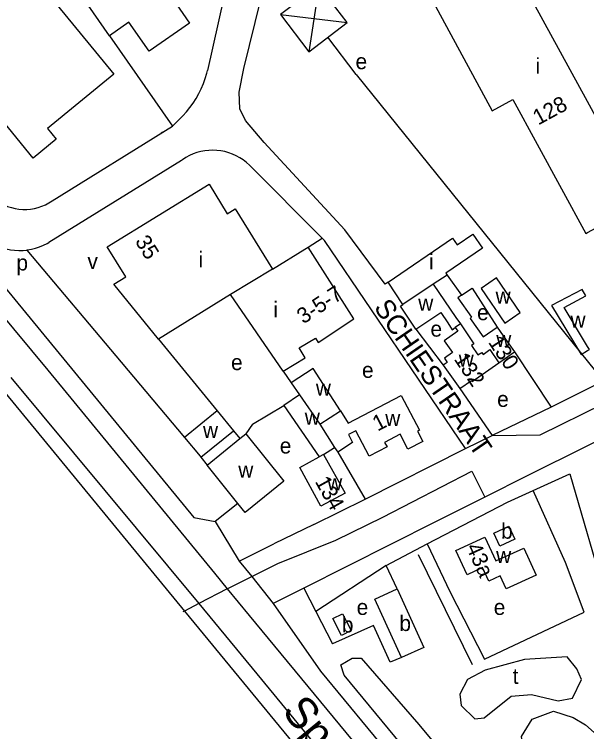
# Model space of a CAD drawing. Extents: x 156721 to 158827, y 386657 to 388950.
# Drawn here: x 157353.3 to 157499.8, y 387526.7 to 387710.2 of the extents above; entities that cross this region are included whole.
import ezdxf

# ---------------------------------------------------------------- set-up
doc = ezdxf.new("R2010")
doc.units = 0
for name, color, linetype in [('BLT_Basislijn', 7, 'Continuous'), ('BLT_Bebouwing', 7, 'Continuous'), ('BLT_Centroide', 7, 'Continuous'), ('BLT_Hoogspanningsmast_en_leidingen', 7, 'Continuous'), ('BLT_Huisnummer', 7, 'Continuous'), ('BLT_Huisnummer_reeks', 7, 'Continuous'), ('BLT_Onderverdeling_panden', 7, 'Continuous'), ('BLT_Spoorlijn', 7, 'Continuous'), ('BLT_Straatnaam', 7, 'Continuous'), ('BLT_Vlakafsluiter', 7, 'Continuous'), ('BLT_Waternaam_spoorwegen', 7, 'Continuous')]:
    doc.layers.add(name, color=color, linetype=linetype)

msp = doc.modelspace()

# ---------------------------------------------------------------- linework, layer by layer
at = {"layer": 'BLT_Basislijn'}
for p, q in [((157410.11, 387729.09), (157402.7, 387695.87)), ((157377.66, 387704.77), (157393.78, 387681.64)), ((157362.98, 387662.49), (157393.78, 387681.64)), ((157396.05, 387672.83), (157362.12, 387651.86)), ((157432.11, 387652.93), (157413.45, 387671.63)), ((157428.48, 387650.64), (157432.11, 387652.93)), ((157356.47, 387649.92), (157380.61, 387621.23)), ((157487.91, 387602.63), (157551.59, 387634.32)), ((157456.09, 387629.7), (157463.07, 387620.46)), ((157531.34, 387630.01), (157490.71, 387609.75)), ((157390.18, 387627.11), (157405.22, 387608.74)), ((157481.29, 387623.9), (157490.71, 387609.75)), ((157380.61, 387621.23), (157396.84, 387601.94)), ((157422.11, 387618.92), (157424.18, 387615.97)), ((157467.28, 387614.46), (157475.55, 387602.45)), ((157414.26, 387605.38), (157422.26, 387610.15)), ((157490.71, 387609.75), (157475.55, 387602.45)), ((157414.26, 387605.38), (157412.54, 387602.88)), ((157409.38, 387603.66), (157411.02, 387601.66)), ((157475.55, 387602.45), (157487.91, 387602.63)), ((157443.08, 387586.2), (157468.77, 387599.15)), ((157436.05, 387598.19), (157443.08, 387586.2)), ((157401.05, 387596.92), (157402.62, 387594.92)), ((157470.39, 387593.34), (157473.69, 387586.73)), ((157484.56, 387592.19), (157473.69, 387586.73)), ((157486.04, 387588.39), (157495.47, 387592.66)), ((157479.52, 387585.43), (157486.04, 387588.39)), ((157429.93, 387579.68), (157443.08, 387586.2)), ((157473.69, 387586.73), (157460.93, 387580.31)), ((157410.52, 387585.07), (157404.73, 387580.46)), ((157458.95, 387574.71), (157479.52, 387585.43)), ((157404.73, 387580.46), (157410.84, 387570.35)), ((157429.93, 387579.68), (157419.68, 387574.71)), ((157460.93, 387580.31), (157427.36, 387563.43)), ((157410.84, 387570.35), (157419.4, 387574.58)), ((157419.4, 387574.58), (157419.68, 387574.71)), ((157448.47, 387569.22), (157458.95, 387574.71)), ((157456.65, 387572.01), (157470.49, 387543.88)), ((157410.84, 387570.35), (157414.06, 387566.36)), ((157414.06, 387566.36), (157420.7, 387569.69)), ((157448.47, 387569.22), (157430.47, 387557.43)), ((157451.27, 387563.26), (157448.47, 387569.22)), ((157414.06, 387566.36), (157419.58, 387559.52)), ((157427.36, 387563.43), (157419.58, 387559.52)), ((157427.36, 387563.43), (157430.47, 387557.43)), ((157430.47, 387557.43), (157434.73, 387549.18))]:
    msp.add_line(p, q, dxfattribs=at)
for points in [[(157166.18, 387865.29), (157399.27, 387581.46), (157404.73, 387580.46)], [(157448.94, 387641.7), (157448.24, 387641.22), (157437.86, 387655.06), (157417.27, 387677.44), (157412.48, 387683.06), (157411.05, 387686.03), (157410.8, 387690.3), (157412, 387696.4), (157429.48, 387767.11), (157430.68, 387770.62), (157433.63, 387777.77)], [(157393.78, 387681.64), (157396.43, 387684.24), (157397.37, 387685.29), (157398.26, 387686.38), (157399.08, 387687.53), (157399.83, 387688.72), (157400.52, 387689.95), (157401.14, 387691.22), (157401.68, 387692.52), (157402.15, 387693.85), (157402.54, 387695.2), (157402.7, 387695.87)], [(157390.9, 387679.9), (157391.29, 387680.15)], [(157413.45, 387671.63), (157412.68, 387672.33), (157411.86, 387672.97), (157411, 387673.54), (157410.09, 387674.04), (157409.15, 387674.47), (157408.18, 387674.83), (157407.18, 387675.11), (157406.17, 387675.31), (157405.14, 387675.43), (157404.1, 387675.48), (157403.07, 387675.44), (157402.04, 387675.32), (157401.02, 387675.13), (157400.02, 387674.86), (157399.05, 387674.51), (157398.1, 387674.09), (157397.19, 387673.59), (157396.33, 387673.03), (157396.05, 387672.83)], [(157346.71, 387664.42), (157347.4, 387663.71), (157348.15, 387663.05), (157348.95, 387662.46), (157349.79, 387661.93), (157350.68, 387661.47), (157351.6, 387661.09), (157352.54, 387660.78), (157353.51, 387660.54), (157354.49, 387660.39), (157355.49, 387660.31), (157356.48, 387660.32), (157357.48, 387660.4), (157358.46, 387660.56), (157359.43, 387660.8), (157360.37, 387661.12), (157361.28, 387661.52), (157362.17, 387661.98), (157362.98, 387662.49)], [(157342.54, 387656.22), (157343.18, 387655.34), (157343.89, 387654.52), (157344.65, 387653.75), (157345.47, 387653.05), (157346.33, 387652.4), (157347.25, 387651.82), (157348.2, 387651.3), (157349.19, 387650.86), (157350.21, 387650.5), (157351.25, 387650.21), (157352.31, 387649.99), (157353.38, 387649.86), (157354.46, 387649.81), (157355.54, 387649.83), (157356.47, 387649.92)], [(157468.77, 387599.15), (157432.7, 387652.33), (157432.11, 387652.93)], [(157356.47, 387649.92), (157356.62, 387649.94), (157357.69, 387650.12), (157358.74, 387650.39), (157359.76, 387650.73), (157360.76, 387651.14), (157361.73, 387651.63), (157362.12, 387651.86)], [(157467.71, 387638.34), (157470.44, 387640.17), (157476.87, 387630.2)], [(157563.26, 387626.61), (157561.05, 387630.2), (157484.56, 387592.19)], [(157420.7, 387569.69), (157435.59, 387575.72), (157447.62, 387581.59), (157470.39, 387593.34)], [(157495.47, 387592.66), (157514.39, 387527.46), (157515.35, 387525.77)], [(157473.59, 387545.22), (157499.15, 387557.25), (157494.35, 387569.94), (157486.04, 387588.39)], [(157458.95, 387574.71), (157464.77, 387562.51), (157473.59, 387545.22)], [(157419.58, 387559.52), (157431.62, 387542.17), (157480.14, 387483.47)], [(157452.41, 387545.62), (157449.48, 387544.49), (157445.2, 387553.88), (157434.73, 387549.18)], [(157648.04, 387289.7), (157544.83, 387414.91), (157472.21, 387499.44), (157437.72, 387541.12), (157436.87, 387543.75), (157439.78, 387545.45), (157442.04, 387545.5), (157456.85, 387528.49), (157499.46, 387477.15), (157606.86, 387347.11), (157687.66, 387250), (157720.52, 387210.5), (157729.65, 387199.36), (157875.7, 387021.05), (157907.43, 386982.75), (157930.36, 386955.08), (157970.6, 386906.98), (158033.86, 386830.67), (158043.03, 386819.55)], [(157485.73, 387516.66), (157483.76, 387520.68), (157483.09, 387525.45), (157485.79, 387529.84), (157491.26, 387531.95), (157496.35, 387530.32), (157499.46, 387528.47), (157504.03, 387524.45), (157506.53, 387521.1)]]:
    msp.add_lwpolyline(points, dxfattribs=at)
msp.add_lwpolyline([(157483.86, 387545.16), (157473.78, 387542.41), (157469.29, 387540.04), (157467.34, 387536.27), (157467.68, 387533.34), (157471.19, 387529.95), (157473.57, 387530.21), (157480.43, 387535.76), (157485.69, 387536.18), (157492.46, 387534.61), (157496.11, 387535.29), (157498.48, 387540.04), (157497.25, 387542.79), (157494.8, 387545.8)], close=True, dxfattribs=at)
at = {"layer": 'BLT_Bebouwing'}
for p, q in [((157427.64, 387650.13), (157428.48, 387650.64)), ((157464.06, 387643.54), (157467.71, 387638.34)), ((157452.69, 387635.99), (157448.94, 387641.7)), ((157408.62, 387638.53), (157390.18, 387627.11)), ((157463.07, 387620.46), (157467.28, 387614.46)), ((157424.18, 387615.97), (157426.28, 387612.91)), ((157426.28, 387612.91), (157422.26, 387610.15)), ((157422.26, 387610.15), (157431.3, 387597)), ((157405.22, 387608.74), (157396.84, 387601.94)), ((157405.22, 387608.74), (157409.38, 387603.66)), ((157401.05, 387596.92), (157409.38, 387603.66)), ((157411.02, 387601.66), (157412.54, 387602.88)), ((157396.84, 387601.94), (157400.84, 387597.19)), ((157402.62, 387594.92), (157411.02, 387601.66)), ((157432.4, 387597.61), (157435.25, 387599.44)), ((157435.25, 387599.44), (157436.05, 387598.19)), ((157400.84, 387597.19), (157401.05, 387596.92)), ((157426.35, 387594.26), (157431.3, 387597)), ((157410.52, 387585.07), (157402.62, 387594.92)), ((157437, 387551.29), (157434.77, 387555.6))]:
    msp.add_line(p, q, dxfattribs=at)
for points in [[(157362.07, 387775.25), (157372.57, 387760.16), (157375.11, 387761.91), (157382.28, 387751.57), (157379.78, 387749.8), (157400.19, 387720.46), (157392.99, 387715.45), (157398.16, 387708), (157387.83, 387700.83), (157382.65, 387708.27), (157377.66, 387704.77)], [(157377.66, 387704.77), (157346.99, 387748.86)], [(157340.65, 387741.36), (157378.75, 387694.96), (157361.77, 387681), (157364.02, 387678.26), (157358.15, 387673.45), (157342.05, 387693.05), (157343.57, 387694.29), (157319.35, 387723.84)], [(157502.52, 387683.28), (157500, 387687.91), (157472.87, 387737.57)], [(157449.47, 387733.79), (157475.61, 387685.56), (157480.9, 387688.44), (157499.58, 387654.16), (157500, 387654.39), (157504.24, 387656.7), (157510.89, 387644.49)], [(157390.18, 387627.11), (157378.76, 387641.19), (157381.81, 387643.08), (157377.05, 387650.73), (157403.15, 387666.75), (157407.8, 387659.2), (157409.86, 387660.46), (157419.34, 387645.05)], [(157448.94, 387641.7), (157465.42, 387652.98), (157466.59, 387651.27), (157470.62, 387654.03), (157473.1, 387650.4), (157463.74, 387643.99), (157464.06, 387643.54)], [(157422.11, 387618.92), (157427.73, 387622.34), (157426.19, 387624.87), (157430.35, 387627.4), (157431.02, 387626.31), (157440.16, 387632.35), (157428.48, 387650.64)], [(157419.34, 387645.05), (157427.64, 387650.13)], [(157500, 387624.19), (157500.47, 387624.47), (157500, 387625.25), (157493.97, 387635.24), (157499.52, 387638.17), (157498.64, 387639.85), (157490.77, 387635.7), (157498.33, 387623.18), (157500, 387624.19)], [(157422.11, 387618.92), (157408.62, 387638.53)], [(157467.71, 387638.34), (157466.8, 387637.71), (157470.3, 387632.71), (157469.94, 387632.45), (157473.28, 387627.68), (157476.87, 387630.2)], [(157456.09, 387629.7), (157452.1, 387635.59), (157452.69, 387635.99)], [(157456.09, 387629.7), (157462.45, 387633.92), (157464.21, 387631.27)], [(157466.32, 387632.67), (157467.46, 387631.03)], [(157464.21, 387631.27), (157465.35, 387629.55), (157466.12, 387630.09)], [(157466.12, 387630.09), (157466.79, 387629.15), (157463.33, 387626.72), (157465.45, 387623.69), (157463.38, 387622.24), (157464.11, 387621.19), (157463.07, 387620.46)], [(157476.87, 387630.2), (157478.42, 387627.99), (157481.29, 387623.9)], [(157477.3, 387621.1), (157481.29, 387623.9)], [(157467.28, 387614.46), (157470.29, 387616.58), (157470.48, 387616.31), (157477.3, 387621.1)], [(157436.75, 387608.74), (157429.82, 387619.61), (157424.18, 387615.97)], [(157452.34, 387612.69), (157456.96, 387603.84), (157456.46, 387603.58), (157457.84, 387600.93), (157454.03, 387598.95), (157452.04, 387602.77), (157448.07, 387600.7), (157448.68, 387599.53), (157444.1, 387597.14), (157440.7, 387603.66), (157438.8, 387602.7), (157439.84, 387600.68), (157436.05, 387598.19)], [(157436.75, 387608.74), (157438.75, 387605.6), (157452.34, 387612.69)], [(157412.54, 387602.88), (157422.26, 387590.76), (157412.34, 387582.8), (157410.52, 387585.07)], [(157432.4, 387597.61), (157437.95, 387587.72), (157431.7, 387584.36), (157426.35, 387594.26)], [(157486.84, 387566.77), (157479.16, 387563.24), (157477.64, 387566.56), (157474.7, 387565.21), (157473.12, 387568.65), (157469.17, 387566.84), (157466.32, 387573.05), (157473.74, 387576.46), (157476.53, 387570.37), (157483.69, 387573.65), (157486.84, 387566.77)], [(157452.41, 387545.62), (157445.54, 387560.63), (157451.27, 387563.26)], [(157451.27, 387563.26), (157458.14, 387548.24), (157452.41, 387545.62)], [(157434.77, 387555.6), (157437.26, 387556.85), (157439.47, 387552.55), (157437, 387551.29)]]:
    msp.add_lwpolyline(points, dxfattribs=at)
for points in [[(157476.71, 387642.78), (157472.73, 387640.05), (157478.8, 387631.22), (157482.78, 387633.95)], [(157476, 387577.49), (157479.86, 387579.27), (157481.41, 387575.91), (157477.55, 387574.13)]]:
    msp.add_lwpolyline(points, close=True, dxfattribs=at)
at = {"layer": 'BLT_Hoogspanningsmast_en_leidingen'}
for p, q in [((157431.24, 387717.61), (157428.67, 387700.66)), ((157421.44, 387710.16), (157438.47, 387708.12)), ((157440.8, 387694.89), (157433.57, 387704.39)), ((157440.8, 387694.89), (157540.64, 387570.92))]:
    msp.add_line(p, q, dxfattribs=at)
msp.add_lwpolyline([(157428.67, 387700.66), (157438.47, 387708.12), (157431.24, 387717.61), (157421.44, 387710.16)], close=True, dxfattribs=at)
at = {"layer": 'BLT_Onderverdeling_panden'}
for p, q in [((157464.06, 387643.54), (157460.51, 387641.18)), ((157460.51, 387641.18), (157452.69, 387635.99)), ((157467.46, 387631.03), (157466.12, 387630.09)), ((157426.28, 387612.91), (157431.48, 387605.33)), ((157431.48, 387605.33), (157436.75, 387608.74)), ((157431.48, 387605.33), (157435.25, 387599.44)), ((157432.4, 387597.61), (157431.3, 387597))]:
    msp.add_line(p, q, dxfattribs=at)
for points in [[(157419.34, 387645.05), (157408.62, 387638.53)], [(157460.51, 387641.18), (157466.32, 387632.67)], [(157467.46, 387631.03), (157470.92, 387625.92), (157470.29, 387625.49), (157471.95, 387623.08), (157472.91, 387623.74), (157473.25, 387623.24), (157474.99, 387624.44), (157477.3, 387621.1)]]:
    msp.add_lwpolyline(points, dxfattribs=at)
at = {"layer": 'BLT_Spoorlijn'}
for p, q in [((157343.68, 387622.16), (157396.85, 387557.55)), ((157352.45, 387617.3), (157400.49, 387559.44)), ((157400.49, 387559.44), (157415.38, 387541.51)), ((157396.85, 387557.55), (157488.81, 387445.81))]:
    msp.add_line(p, q, dxfattribs=at)
for points in [[(157301.57, 387691.68), (157361.84, 387619.18)], [(157361.84, 387619.18), (157404.5, 387567.21)], [(157404.5, 387567.21), (157407.79, 387563.21)], [(157407.79, 387563.21), (157413.38, 387556.4)], [(157413.38, 387556.4), (157476.28, 387480.28)], [(157415.38, 387541.51), (157472.53, 387471.98)]]:
    msp.add_lwpolyline(points, dxfattribs=at)
at = {"layer": 'BLT_Vlakafsluiter'}
for p, q in [((157468.77, 387599.15), (157475.55, 387602.45)), ((157407.79, 387563.21), (157414.06, 387566.36)), ((157407.79, 387563.21), (157400.49, 387559.44)), ((157400.49, 387559.44), (157396.85, 387557.55)), ((157396.85, 387557.55), (157396.39, 387557.32))]:
    msp.add_line(p, q, dxfattribs=at)

# ---------------------------------------------------------------- texts
at = {"layer": 'BLT_Centroide'}
for s, p in [('e', (157440.62, 387696.21)), ('i', (157486.69, 387695.05)), ('i', (157400.43, 387645.54)), ('i', (157459.42, 387644.97)), ('p', (157353.83, 387644.7)), ('v', (157372.02, 387645.09)), ('w', (157476.46, 387636.22)), ('i', (157419.57, 387632.72)), ('w', (157456.66, 387634.39)), ('e', (157471.72, 387631.98)), ('w', (157495.62, 387630.08)), ('e', (157459.8, 387627.77)), ('w', (157476.63, 387625.15)), ('w', (157467.02, 387620.12)), ('e', (157408.76, 387619.2)), ('e', (157442.28, 387617.22)), ('w', (157430.47, 387612.7)), ('e', (157476.86, 387609.79)), ('w', (157427.63, 387605.2)), ('w', (157448.22, 387604.91)), ('w', (157401.58, 387601.84)), ('e', (157421.23, 387597.86)), ('w', (157410.61, 387591.7)), ('w', (157433.37, 387588.48)), ('b', (157477.87, 387576.06)), ('w', (157476.6, 387569.84)), ('e', (157440.91, 387556.55)), ('e', (157475.99, 387556.55)), ('b', (157437.12, 387552.06)), ('b', (157451.84, 387552.44)), ('t', (157480.83, 387538.9))]:
    msp.add_text(s, height=4, dxfattribs=at).set_placement(p)
at = {"layer": 'BLT_Huisnummer'}
for s, rotation, p in [('128', 28.5877, (157487.37, 387681.78)), ('35', 301.5897, (157384.08, 387652.18)), ('130', 303.5813, (157474.44, 387626.33)), ('132', 303.5813, (157465.69, 387622.02)), ('1', 27.5384, (157446.27, 387603.45)), ('134', 298.9589, (157430.14, 387590.72)), ('43a', 294.6327, (157468.82, 387573.91))]:
    msp.add_text(s, height=4, rotation=rotation, dxfattribs=at).set_placement(p)
at = {"layer": 'BLT_Huisnummer_reeks'}
msp.add_text('3-5-7', height=4, rotation=33.4885, dxfattribs=at).set_placement((157427.28, 387630.87))
at = {"layer": 'BLT_Straatnaam'}
msp.add_text('SCHIESTRAAT', height=5, rotation=304.5385, dxfattribs=at).set_placement((157445.16, 387635.21))
at = {"layer": 'BLT_Waternaam_spoorwegen'}
msp.add_text('Spoorlijn', height=8, rotation=309.1535, dxfattribs=at).set_placement((157421.59, 387531.78))

doc.saveas('drawing.dxf')
